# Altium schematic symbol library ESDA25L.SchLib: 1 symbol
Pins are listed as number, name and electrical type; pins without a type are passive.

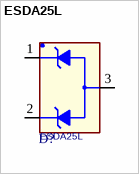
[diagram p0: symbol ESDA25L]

## ESDA25L
designator D?
footprint ST_SOT23-3L
pins: 1 K1, 2 K2, 3 A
